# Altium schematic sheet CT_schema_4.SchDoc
size 527 x 503 mm
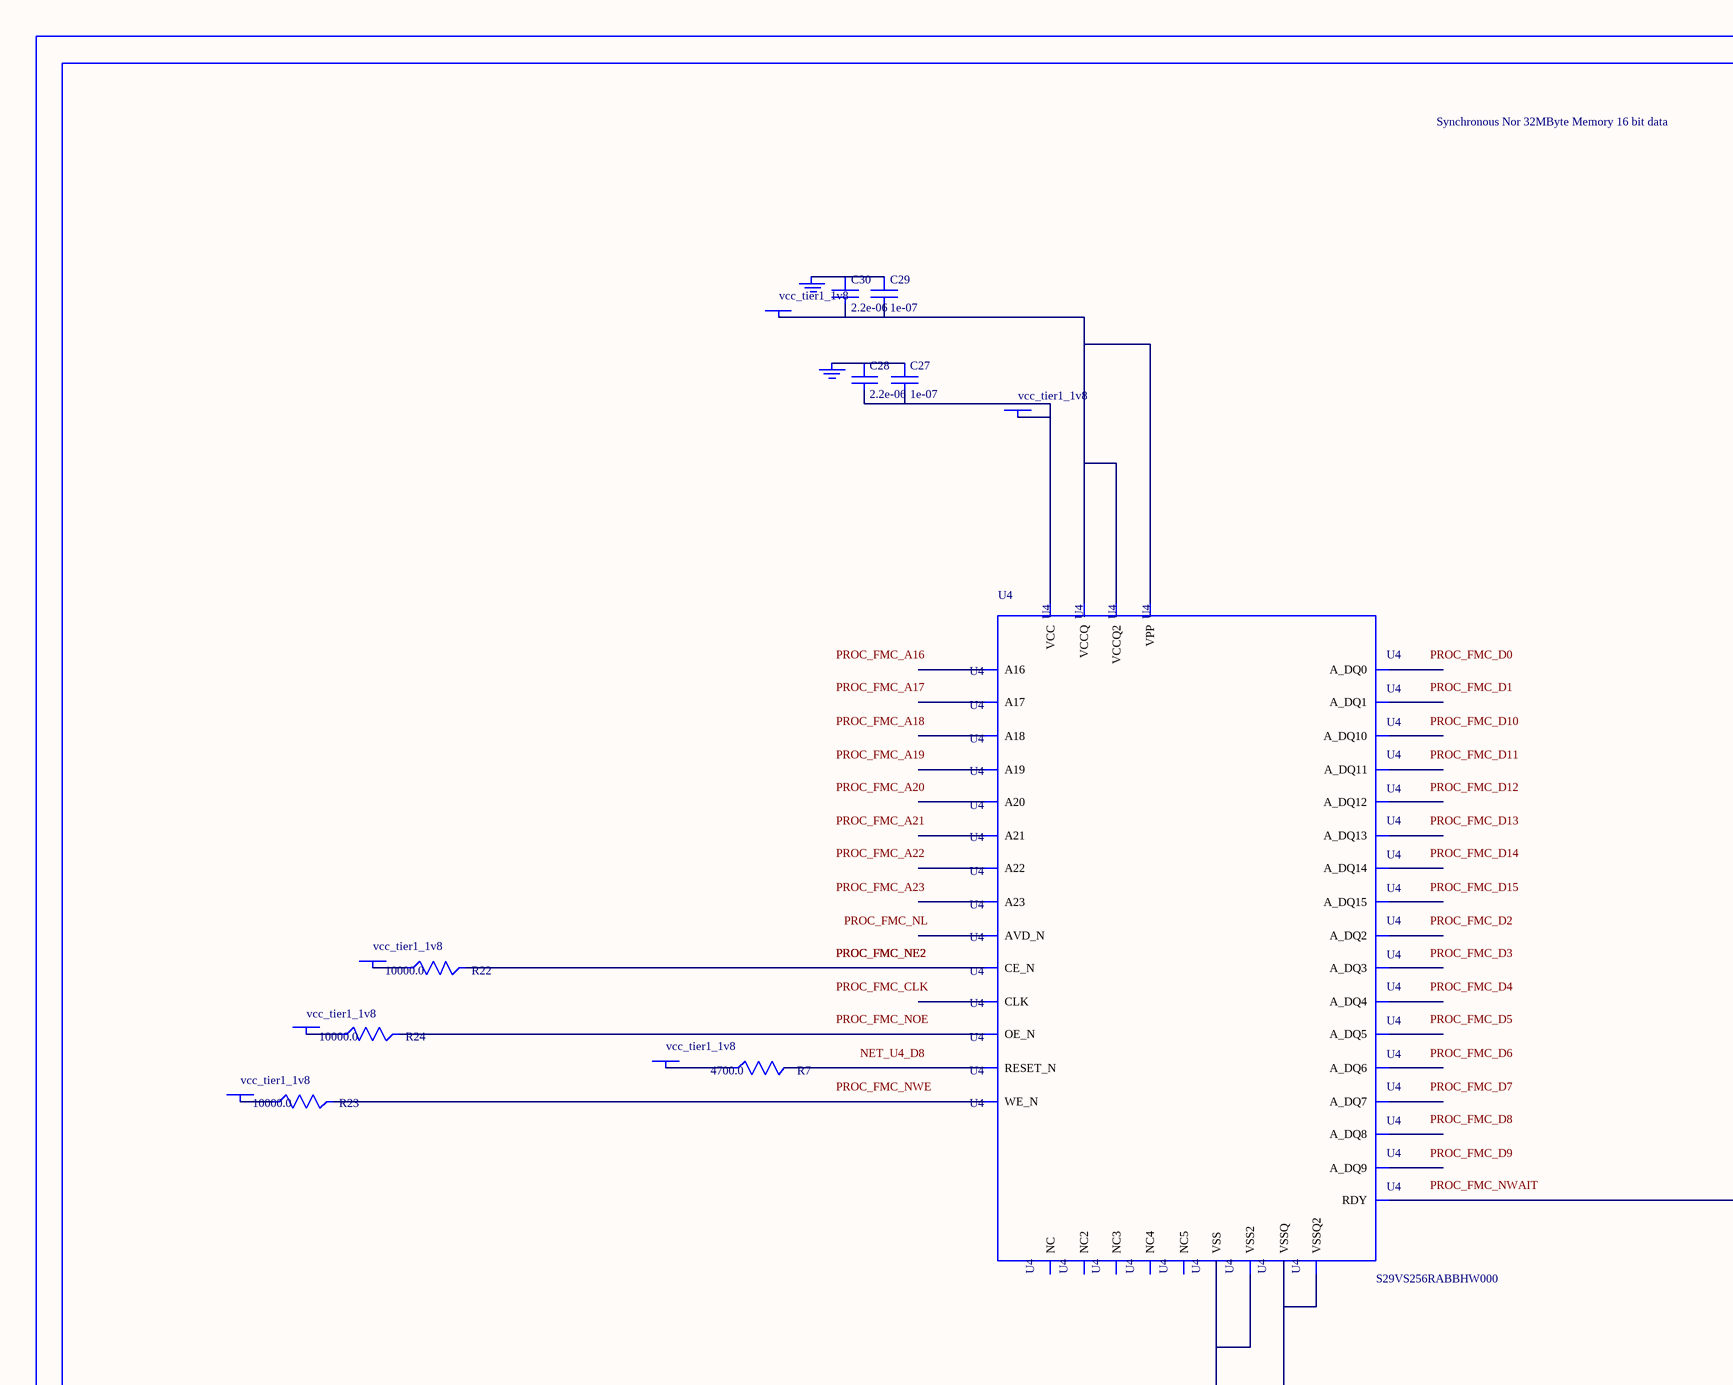
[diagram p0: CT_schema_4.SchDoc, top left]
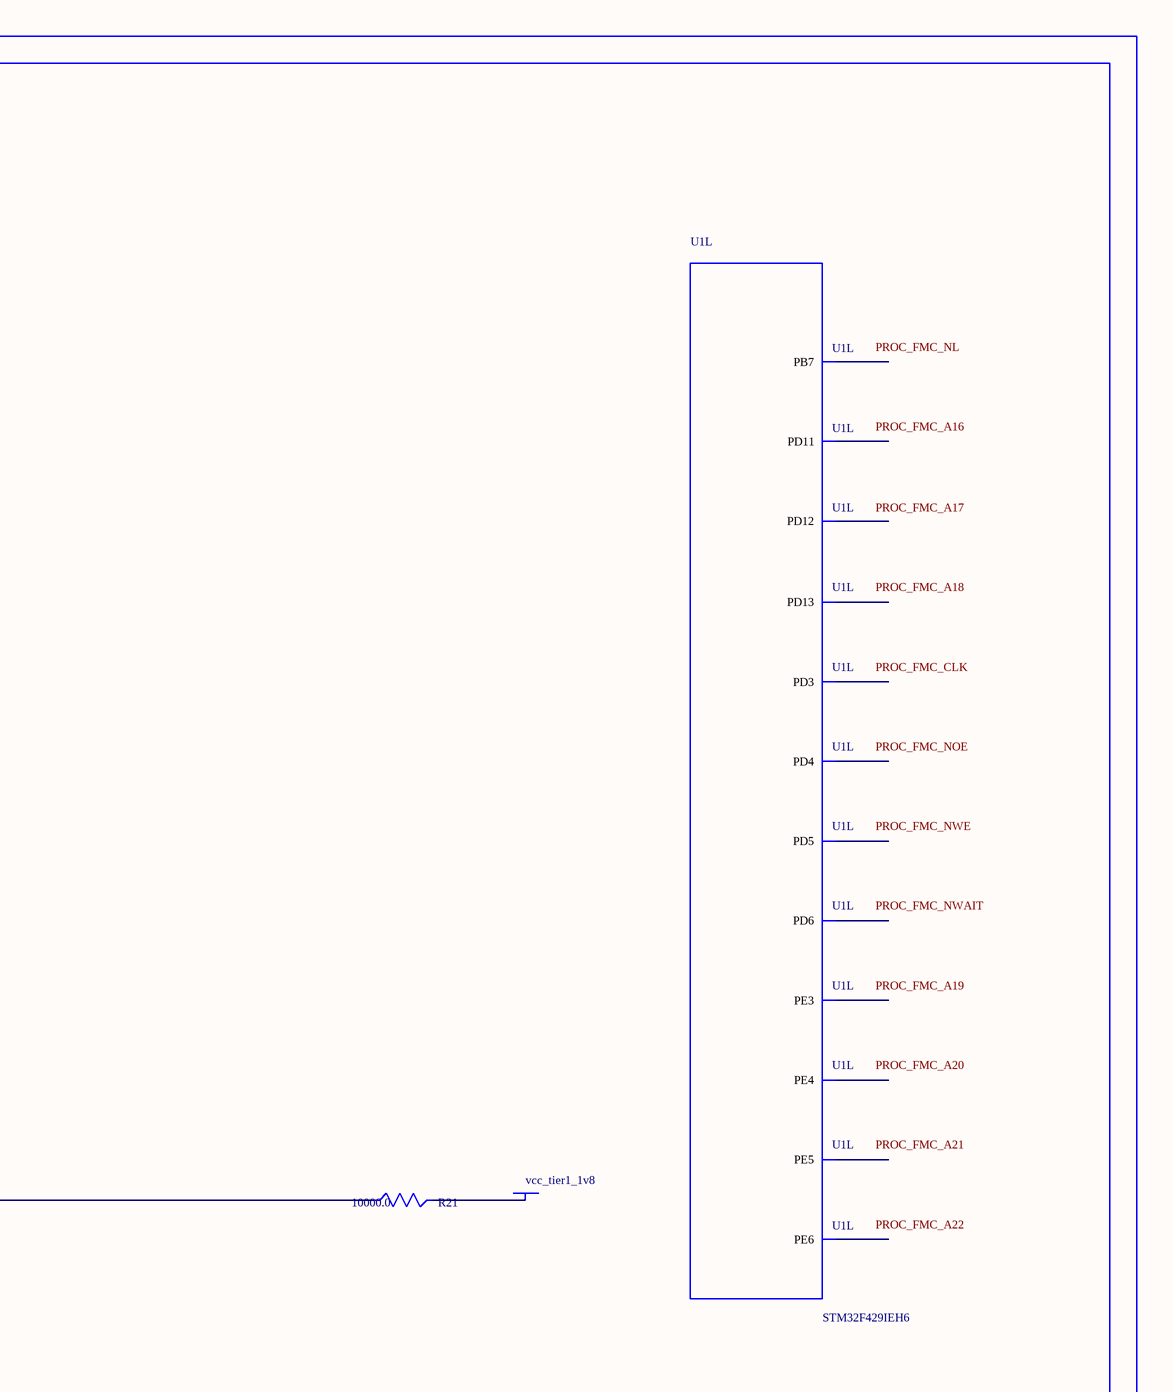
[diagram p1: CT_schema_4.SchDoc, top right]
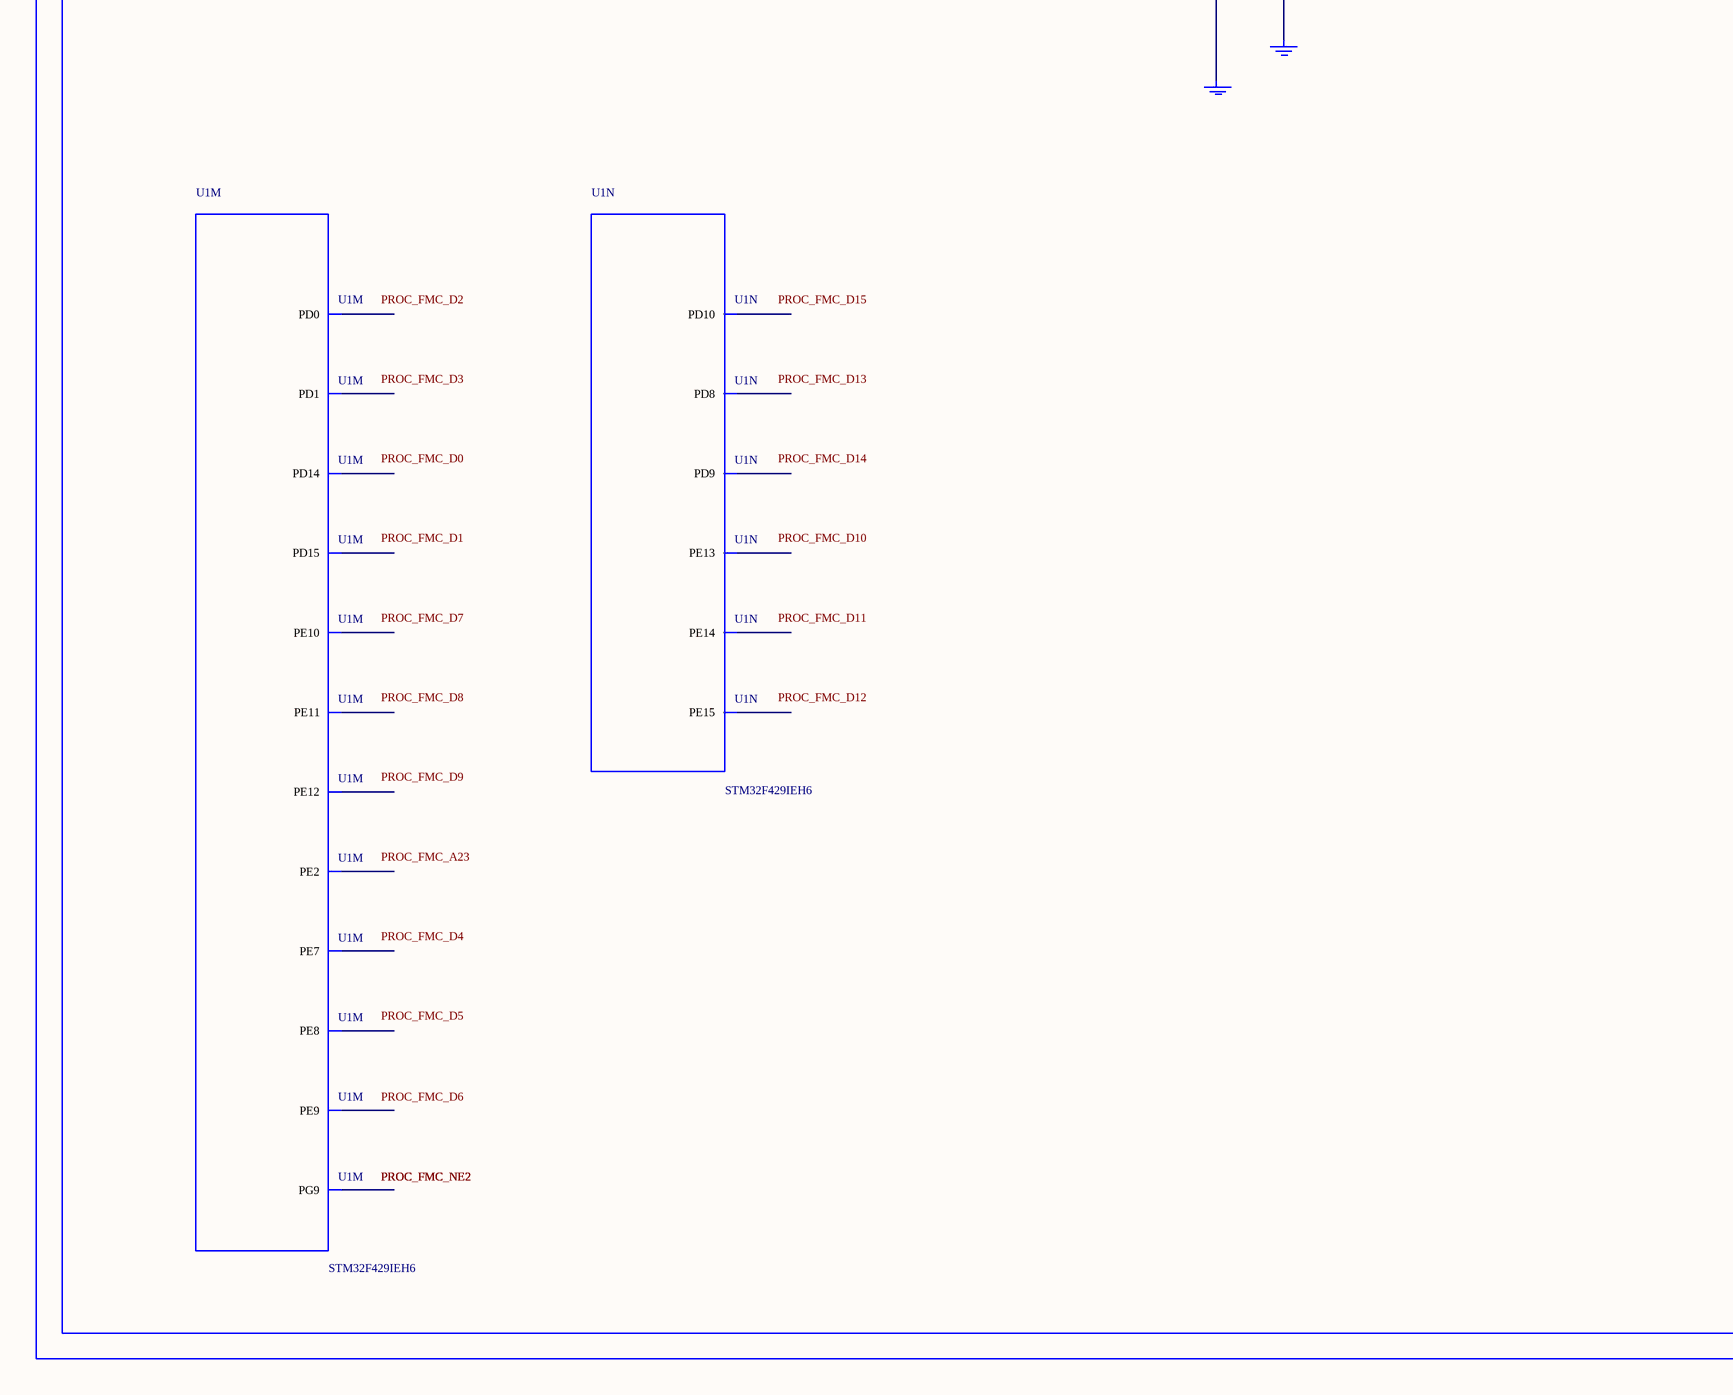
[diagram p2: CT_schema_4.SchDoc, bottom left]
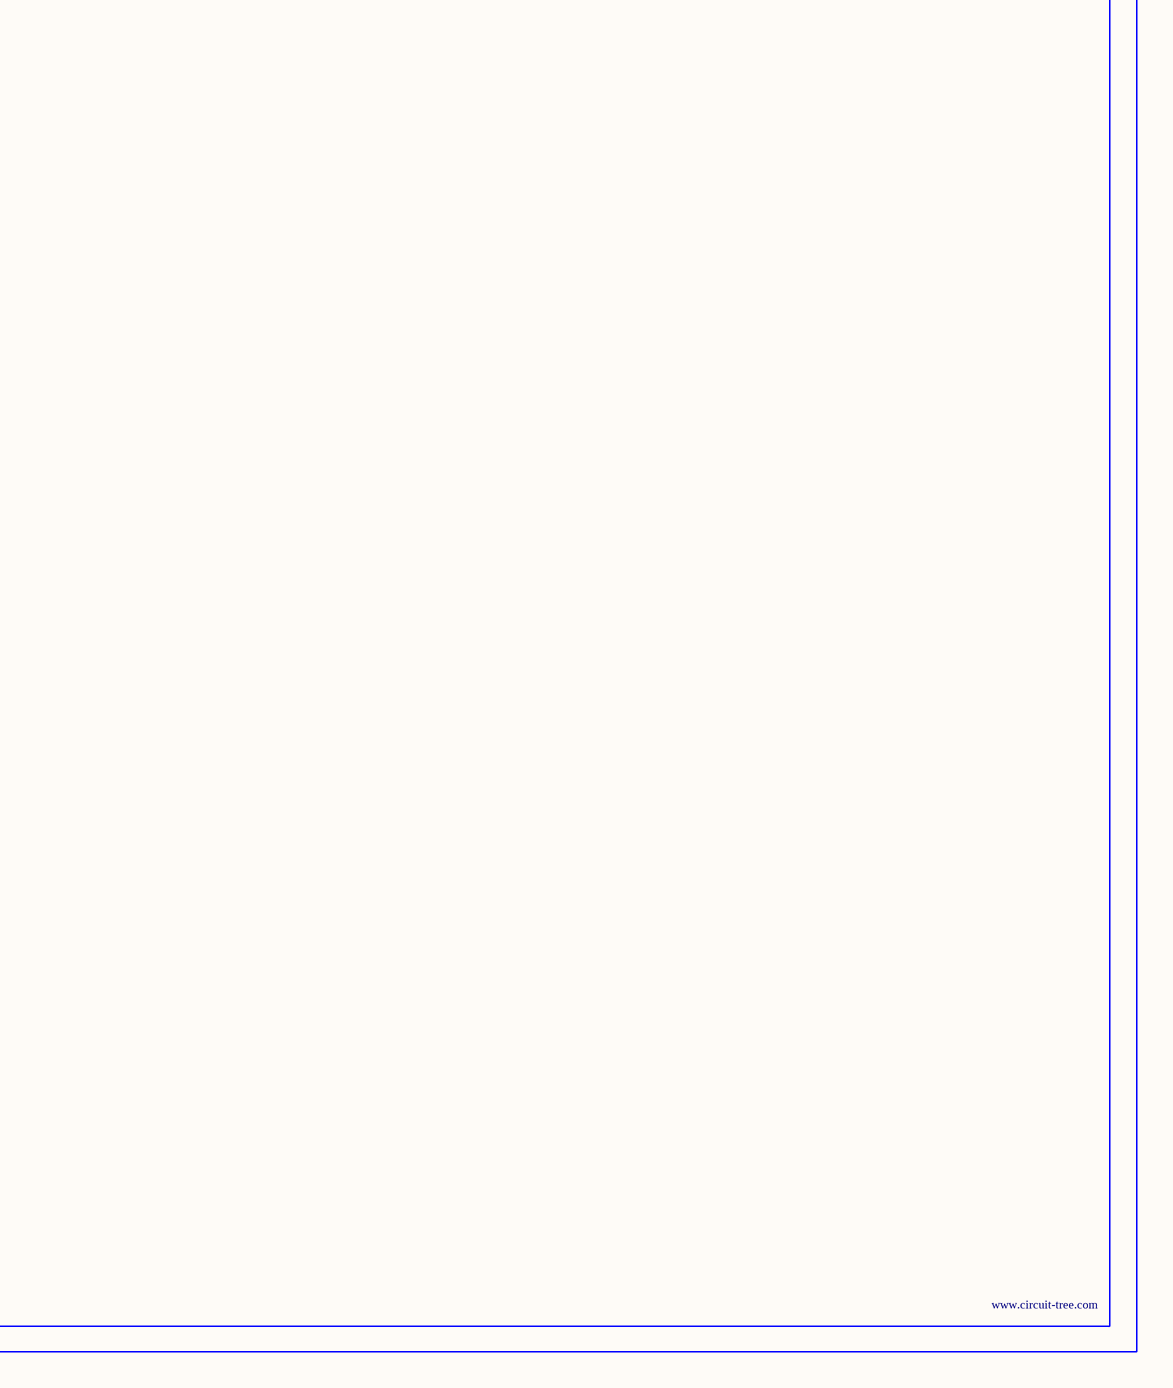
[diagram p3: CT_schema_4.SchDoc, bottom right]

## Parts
BORDER3  (no value)
C27  1e-07  [C0402]
C28  2.2e-06  [C0603]
C29  1e-07  [C0402]
C30  2.2e-06  [C0603]
GND_INSTANCE_3_0  (no value)
GND_INSTANCE_3_1  (no value)
GND_INSTANCE_3_2  (no value)
GND_INSTANCE_3_3  (no value)
POWER_INSTANCE_3_0  vcc_tier1_1v8
POWER_INSTANCE_3_1  vcc_tier1_1v8
POWER_INSTANCE_3_2  vcc_tier1_1v8
POWER_INSTANCE_3_3  vcc_tier1_1v8
POWER_INSTANCE_3_4  vcc_tier1_1v8
POWER_INSTANCE_3_5  vcc_tier1_1v8
POWER_INSTANCE_3_6  vcc_tier1_1v8
R7  4700.0  [R0603]
R21  10000.0  [R0603]
R22  10000.0  [R0603]
R23  10000.0  [R0603]
R24  10000.0  [R0603]
U1  STM32F429IEH6  [UFBGA176_25]  (parts L,M,N of 15)
U4  S29VS256RABBHW000  [S29VS256RABBHW000]

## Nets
NetC27_1: C27.1 C28.1 GND_INSTANCE_3_0.0(GND)
NetC27_2: C27.2 C28.2 POWER_INSTANCE_3_0.0(PWR) U4.C7(VCC)
NetC29_1: C29.1 C30.1 GND_INSTANCE_3_1.0(GND)
NetC29_2: C29.2 C30.2 POWER_INSTANCE_3_1.0(PWR) U4.C9(VPP) U4.D3(VCCQ) U4.F10(VCCQ2)
NetGND_INSTANCE_3_2_0: GND_INSTANCE_3_2.0(GND) U4.C5(VSS) U4.D12(VSS2)
NetGND_INSTANCE_3_3_0: GND_INSTANCE_3_3.0(GND) U4.E3(VSSQ) U4.F5(VSSQ2)
NetPOWER_INSTANCE_3_2_0: POWER_INSTANCE_3_2.0(PWR) R21.2
NetPOWER_INSTANCE_3_3_0: POWER_INSTANCE_3_3.0(PWR) R22.1
NetPOWER_INSTANCE_3_4_0: POWER_INSTANCE_3_4.0(PWR) R23.1
NetPOWER_INSTANCE_3_5_0: POWER_INSTANCE_3_5.0(PWR) R24.1
NetPOWER_INSTANCE_3_6_0: POWER_INSTANCE_3_6.0(PWR) R7.1
NetR7_2: R7.2 U4.D8(RESET_N)
NetR21_1: R21.1 U4.C3(RDY)
NetR22_2: R22.2 U4.D11(CE_N)
NetR23_2: R23.2 U4.C8(WE_N)
NetR24_2: R24.2 U4.E12(OE_N)

Not connected (* = marked no-connect by the designer): U1 A1(PE3) A2(PE2) B1(PE4) B2(PE5) B3(PE6) B5(PB7) B11(PD6) B12(PD0) C10(PG9) C11(PD5) C12(PD1) D10(PD4) D11(PD3) L14(PD15) M14(PD14) M15(PD13) N11(PE13) N13(PD12) N14(PD11) N15(PD10) P8(PE8) P9(PE9) P10(PE11) P11(PE14) P14(PD9) P15(PD8) R8(PE7) R9(PE10) R10(PE12) R11(PE15); U4 A1(NC) A14(NC2) C4(A21) C6(CLK) C10(A19) C11(A17) C12(A22) D4(A16) D5(A20) D6(AVD_N) D7(A23) D9(NC3) D10(A18) E4(A_DQ8) E5(A_DQ9) E6(A_DQ2) E7(A_DQ3) E8(A_DQ12) E9(A_DQ13) E10(A_DQ6) E11(A_DQ7) F3(A_DQ0) F4(A_DQ1) F6(A_DQ10) F7(A_DQ11) F8(A_DQ4) F9(A_DQ5) F11(A_DQ14) F12(A_DQ15) H1(NC4) H14(NC5)

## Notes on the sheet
- Labels drawn without touching a wire or pin: NET_U4_D8, PROC_FMC_A16, PROC_FMC_A17, PROC_FMC_A18, PROC_FMC_A19, PROC_FMC_A20, PROC_FMC_A21, PROC_FMC_A22, PROC_FMC_A23, PROC_FMC_CLK, PROC_FMC_D0, PROC_FMC_D1, PROC_FMC_D2, PROC_FMC_D3, PROC_FMC_D4, PROC_FMC_D5, PROC_FMC_D6, PROC_FMC_D7, PROC_FMC_D8, PROC_FMC_D9, PROC_FMC_D10, PROC_FMC_D11, PROC_FMC_D12, PROC_FMC_D13, PROC_FMC_D14, PROC_FMC_D15, PROC_FMC_NL, PROC_FMC_NOE, PROC_FMC_NWAIT, PROC_FMC_NWE

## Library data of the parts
BORDER3 = BORDER_PAGE3
C27 C29 = C0402C104K3RACTU
C28 C30 = C0603C225K8RACTU
GND_INSTANCE_3_0-GND_INSTANCE_3_3 = GND
POWER_INSTANCE_3_0-POWER_INSTANCE_3_6 = PWR
R7 = RC0603JR-074K7L
R21-R24 = RC0603JR-0710KL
